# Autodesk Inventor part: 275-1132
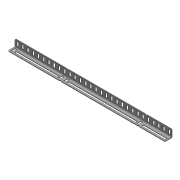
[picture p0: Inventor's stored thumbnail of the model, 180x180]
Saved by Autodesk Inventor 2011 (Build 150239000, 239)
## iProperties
Company: Autodesk Inc.
Created: 2005-08
Part Number: 275-1132
Document SubType Name: Sheet Metal
Designer: Autodesk Inc.
Density: 1 g/cm^3
Sheet Metal Rule: Default
Catalog Web Link: http://www.vexrobotics.com/products/accessories/structure/segmented-angle.html
Description: VEX angle with holes and slots identical to the standard VEX kit. Can be cut to 5, 10, 15, 20 or 25 hole lengths.
Vendor: Innovation First, Inc.
Author: Autodesk Inc.
Title: VEX Robotics Kit of Parts
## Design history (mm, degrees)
node "Face1"
  sketch "Sketch1"
    geometry: L1 (-186.436, 13.081)-(-181.864, 13.081); L2 (-181.864, 13.081)-(-181.864, 3.302); L3 (-181.864, 3.302)-(-186.436, 3.302); L4 (-186.436, 3.302)-(-186.436, 13.081); L5 (-190.5, 14.605)-(-190.5, 0); L6 (190.5, 14.605)-(190.5, 0); L7 (-188.595, 16.51)-(-65.405, 16.51); L8 (-190.5, 0)-(190.5, 0); L9 (-63.5, 14.605)-(-63.5, 0); L10 (-63.5, 14.605)-(-65.405, 16.51); L11 (-188.595, 16.51)-(-190.5, 14.605); L12 (-173.736, 3.302)-(-173.736, 13.081); L13 (-169.164, 3.302)-(-173.736, 3.302); L14 (-169.164, 13.081)-(-169.164, 3.302); L15 (-173.736, 13.081)-(-169.164, 13.081); L16 (-161.036, 3.302)-(-161.036, 13.081); L17 (-156.464, 3.302)-(-161.036, 3.302); L18 (-156.464, 13.081)-(-156.464, 3.302); L19 (-161.036, 13.081)-(-156.464, 13.081); L20 (-148.336, 3.302)-(-148.336, 13.081); L21 (-143.764, 3.302)-(-148.336, 3.302); L22 (-143.764, 13.081)-(-143.764, 3.302); L23 (-148.336, 13.081)-(-143.764, 13.081); L24 (-135.636, 3.302)-(-135.636, 13.081); L25 (-131.064, 3.302)-(-135.636, 3.302); L26 (-131.064, 13.081)-(-131.064, 3.302); L27 (-135.636, 13.081)-(-131.064, 13.081); L28 (-122.936, 3.302)-(-122.936, 13.081); L29 (-118.364, 3.302)-(-122.936, 3.302); L30 (-118.364, 13.081)-(-118.364, 3.302); L31 (-122.936, 13.081)-(-118.364, 13.081); L32 (-110.236, 3.302)-(-110.236, 13.081); L33 (-105.664, 3.302)-(-110.236, 3.302); L34 (-105.664, 13.081)-(-105.664, 3.302); L35 (-110.236, 13.081)-(-105.664, 13.081); L36 (-97.536, 3.302)-(-97.536, 13.081); L37 (-92.964, 3.302)-(-97.536, 3.302); L38 (-92.964, 13.081)-(-92.964, 3.302); L39 (-97.536, 13.081)-(-92.964, 13.081); L40 (-84.836, 3.302)-(-84.836, 13.081); L41 (-80.264, 3.302)-(-84.836, 3.302); L42 (-80.264, 13.081)-(-80.264, 3.302); L43 (-84.836, 13.081)-(-80.264, 13.081); L44 (-72.136, 3.302)-(-72.136, 13.081); L45 (-67.564, 3.302)-(-72.136, 3.302); L46 (-67.564, 13.081)-(-67.564, 3.302); L47 (-72.136, 13.081)-(-67.564, 13.081); L48 (-59.436, 3.302)-(-59.436, 13.081); L49 (-54.864, 3.302)-(-59.436, 3.302); L50 (-54.864, 13.081)-(-54.864, 3.302); L51 (-59.436, 13.081)-(-54.864, 13.081); L52 (-46.736, 3.302)-(-46.736, 13.081); L53 (-42.164, 3.302)-(-46.736, 3.302); L54 (-42.164, 13.081)-(-42.164, 3.302); L55 (-46.736, 13.081)-(-42.164, 13.081); L56 (-34.036, 3.302)-(-34.036, 13.081); L57 (-29.464, 3.302)-(-34.036, 3.302); L58 (-29.464, 13.081)-(-29.464, 3.302); L59 (-34.036, 13.081)-(-29.464, 13.081); L60 (-21.336, 3.302)-(-21.336, 13.081); L61 (-16.764, 3.302)-(-21.336, 3.302); L62 (-16.764, 13.081)-(-16.764, 3.302); L63 (-21.336, 13.081)-(-16.764, 13.081); L64 (-8.636, 3.302)-(-8.636, 13.081)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; 6 further points
    constraints: 268 end point, 10 point on line, 5 parallel, 5 perpendicular, 2 horizontal, 2 symmetric about line, 1 coincident, 1 midpoint, 232 other
    dimensions: "d1" = 4.064 distance between parallel lines of L4 L5; "d2" = 9.779 distance between parallel lines of L3 L1; "d3" = 4.572 distance of L1.start L1.end; "d12" = 16.51 distance of point (-190.5, 16.51) L5.end; "d14" = 1.905 distance of L9.start point (-63.5, 16.51); "d15" = 1.905 distance of L7.end point (-63.5, 16.51) (= d14); "d16" = 1.905 distance of L7.start point (-190.5, 16.51); "d17" = 1.905 distance of L5.start point (-190.5, 16.51) (= d16); "d20" = 12.7 distance of L3.end L12.start; "d26" = 1.905 distance of L130.start point (127, 16.51); "d27" = 1.905 distance of L129.end point (127, 16.51) (= d26); "d28" = 1.905 distance of L6.start point (190.5, 16.51); "d29" = 1.905 distance of L133.end point (190.5, 16.51) (= d28); "d86" = 3.429 distance between parallel lines of L7 L1; "d87" = 127 distance between parallel lines of L5 L9; "d88" = 63.5 distance between parallel lines of L6 L130; "d89" = 381 distance of L5.end L6.end
node "Flange1"
feature "Corner Chamfer1" dims "d38" = 1.905, "d39" = 6.35, angle "d40" = 45 deg
sketch "Sketch3"
  geometry: L1 (381, -13.741)-(381, 0) reference; L2 (0, 0)-(0, -13.741) reference; L3 (1.905, -15.646)-(379.095, -15.646) reference; L4 (11.684, -7.01)-(115.316, -7.01); L5 (115.316, -7.01)-(115.316, -11.582); L6 (115.316, -11.582)-(11.684, -11.582); L7 (11.684, -11.582)-(11.684, -7.01); L8 (317.5, -13.741)-(317.5, 0); L9 (317.5, -13.741)-(315.595, -15.646); L10 (317.5, -13.741)-(319.405, -15.646); L11 (308.864, -2.438)-(313.436, -2.438); L12 (313.436, -2.438)-(313.436, -12.217); L13 (313.436, -12.217)-(308.864, -12.217); L14 (308.864, -12.217)-(308.864, -2.438); L15 (138.684, -7.01)-(305.816, -7.01); L16 (305.816, -7.01)-(305.816, -11.582); L17 (305.816, -11.582)-(138.684, -11.582); L18 (138.684, -11.582)-(138.684, -7.01); L19 (118.364, -2.438)-(122.936, -2.438); L20 (122.936, -2.438)-(122.936, -12.217); L21 (122.936, -12.217)-(118.364, -12.217); L22 (118.364, -12.217)-(118.364, -2.438); L23 (127, 0)-(127, -13.741); L24 (125.095, -15.646)-(127, -13.741); L25 (128.905, -15.646)-(127, -13.741); L26 (131.064, -2.438)-(135.636, -2.438); L27 (135.636, -2.438)-(135.636, -12.217); L28 (135.636, -12.217)-(131.064, -12.217); L29 (131.064, -12.217)-(131.064, -2.438); L30 (320.802, -7.01)-(377.698, -7.01); L31 (377.698, -7.01)-(377.698, -11.582); L32 (377.698, -11.582)-(320.802, -11.582); L33 (320.802, -11.582)-(320.802, -7.01); L34 (4.064, -2.438)-(8.636, -2.438); L35 (8.636, -2.438)-(8.636, -12.217); L36 (8.636, -12.217)-(4.064, -12.217); L37 (4.064, -12.217)-(4.064, -2.438); L38 (0, 0)-(381, 0) reference; L39 (315.595, -15.646)-(319.405, -15.646); L40 (125.095, -15.646)-(128.905, -15.646); L41 (1.905, -15.646)-(0, -13.741) reference; 2 further points
  constraints: 72 end point, 18 parallel, 13 collinear, 7 horizontal, 7 perpendicular, 4 point on line, 2 symmetric about line
  dimensions: "d42" = 4.064 distance between parallel lines of L3 L6; "d43" = 4.572 distance between parallel lines of L4 L6; "d45" = 1.905 distance of L8.start point (317.5, -15.646); "d46" = 1.905 distance of L9.end point (317.5, -15.646) (= d45); "d49" = 4.572 distance of L11.start L11.end; "d50" = 3.429 distance between parallel lines of L3 L13; "d51" = 9.779 distance of L11.end L12.end; "d56" = 4.572 distance of L20.end L21.end; "d58" = 1.905 distance of L24.start point (127, -15.646); "d59" = 1.905 distance of L23.end point (127, -15.646) (= d58); "d61" = 4.064 distance between parallel lines of L23 L20; "d62" = 4.064 distance between parallel lines of L29 L23; "d63" = 4.572 distance between parallel lines of L29 L27; "d68" = 4.572 distance between parallel lines of L35 L37; "d93" = 4.064 distance between parallel lines of L8 L12; "d94" = 3.302 distance between parallel lines of L1 L31; "d95" = 63.5 distance between parallel lines of L1 L8; "d96" = 3.302 distance between parallel lines of L33 L8; "d97" = 3.048 distance between parallel lines of L14 L16; "d98" = 4.064 distance between parallel lines of L37 L2; "d99" = 3.048 distance between parallel lines of L7 L35; "d100" = 3.048 distance between parallel lines of L22 L5; "d101" = 3.048 distance between parallel lines of L18 L27; "d102" = 177.8 distance between parallel lines of L27 L12
cut "Cut1" sketch "Sketch3" dims "d69" = 1.27 (= Thickness), "d70" = 0
sketch "Sketch5"
  geometry: L1 (317.5, -13.741)-(319.405, -15.646) reference; L2 (0, 0)-(381, 0) reference; L3 (315.595, 1.118)-(317.5, -0.787); L4 (317.5, -0.787)-(319.405, 1.118); L5 (319.405, 1.118)-(317.5, 3.023); L6 (317.5, 3.023)-(315.595, 1.118); L7 (125.095, 1.118)-(127, -0.787); L8 (127, -0.787)-(128.905, 1.118); L9 (128.905, 1.118)-(127, 3.023); L10 (127, 3.023)-(125.095, 1.118); 5 further points
  constraints: 16 end point, 6 vertical alignment, 5 parallel, 3 perpendicular, 2 horizontal alignment
  dimensions: "d82" = 1.1176 distance from line of L2 L3.start; "d83" = 1.1176 distance from line of L2 L7.start
cut "Cut2" sketch "Sketch5" dims "d84" = 1.27 (= Thickness), "d85" = 0
body "Solid1"
face "Plate1" dims "Thickness" = 1.27
sketch "Sketch2"
  geometry: L1 (381, 0)-(381, 16.51); L2 (381, 16.51)-(0, 16.51); 2 other entities
  constraints: 4 end point, 4 other
face "Plate2" dims "d31" = 1.27 (= BendReliefWidth), "d33" = 2.54 (= MinimumRemnant), "d35" = 16.51, "d36" = 90 deg, "d37" = 0.8636, "Thickness" = 1.27
bend "Bend1" dims "d31" = 1.27 (= BendReliefWidth), "d32" = 0.635 (= BendReliefDepth), "d33" = 2.54 (= MinimumRemnant), "d34" = 1.27 (= BendRadius), "d35" = 16.51, "d36" = 90 deg, "d37" = 0.8636, "SeamGap" = 0.00508, "Thickness" = 1.27
other parameters: "BendRadius" = 1.27 (= Thickness), "BendReliefWidth" = 1.27 (= Thickness), "BendReliefDepth" = 0.635 (= 0.5 x Thickness), "CornerReliefSize" = 5.08 (= 4 x Thickness), "MinimumRemnant" = 2.54 (= 2 x Thickness), "TransitionRadius" = 1.27 (= BendRadius), "d23" = 25.4, "d30" = 1.27 (= BendRadius), "JacobiRadiusSize" = 1.27 (= Thickness), "GapSize" = 1.27 (= Thickness)
